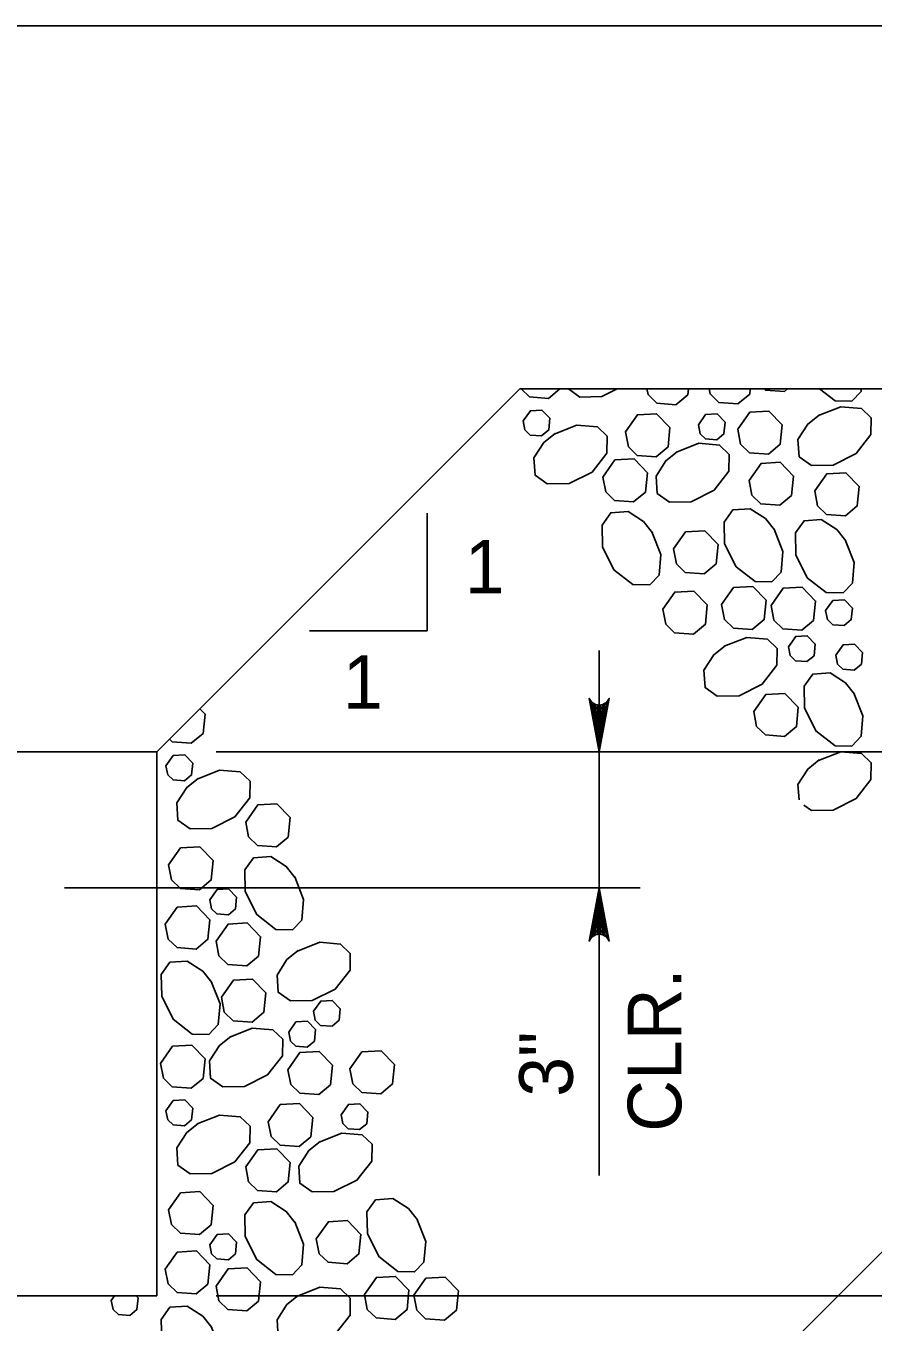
# Model space of a CAD drawing. Extents: x 638079 to 640019, y 297691 to 298879.
# Drawn here: x 639410.8 to 639458.2, y 298729 to 298801.6 of the extents above; entities that cross this region are included whole.
import ezdxf

# ---------------------------------------------------------------- set-up
doc = ezdxf.new("R2010")
doc.units = 0
doc.layers.add('1', color=7, linetype='Continuous')

msp = doc.modelspace()

# ---------------------------------------------------------------- linework, layer by layer
at = {"layer": '1'}
for p, q in [((639342.891, 298801.575), (639493.433, 298801.575)), ((639418.14, 298760.936), (639438.458, 298781.254)), ((639438.458, 298781.254), (639493.433, 298781.254)), ((639433.273, 298774.284), (639433.273, 298767.699)), ((639433.273, 298767.699), (639426.688, 298767.699)), ((639442.891, 298737.206), (639442.891, 298766.595)), ((639265.74, 298760.936), (639418.14, 298760.936)), ((639418.14, 298760.936), (639418.14, 298730.456)), ((639421.456, 298760.936), (639505.834, 298760.936)), ((639433.38, 298707.596), (639484.178, 298758.394)), ((639412.971, 298753.316), (639445.183, 298753.316)), ((639265.74, 298730.456), (639418.14, 298730.456)), ((639421.456, 298730.456), (639506.188, 298730.456))]:
    msp.add_line(p, q, dxfattribs=at)
msp.add_lwpolyline([(639488.261, 298789.413), (639493.433, 298791.946), (639493.433, 298801.575), (639342.891, 298801.575), (639342.891, 298799.67), (639341.94, 298799.67), (639341.94, 298760.936), (639418.14, 298760.936), (639438.458, 298781.254), (639493.433, 298781.254), (639493.433, 298788.428), (639498.394, 298790.783)], close=True, dxfattribs=at)
for points in [[(639440.691, 298781.254), (639440.051, 298780.721), (639438.991, 298780.798), (639438.52, 298781.254)], [(639443.904, 298781.254), (639443.03, 298780.817), (639441.816, 298780.796), (639441.171, 298781.254)], [(639447.881, 298781.254), (639447.848, 298780.918), (639447.185, 298780.366), (639446.125, 298780.443), (639445.626, 298780.927), (639445.563, 298781.254)], [(639451.346, 298781.254), (639451.316, 298780.957), (639450.653, 298780.406), (639449.593, 298780.483), (639449.095, 298780.966), (639449.039, 298781.254)], [(639453.437, 298781.254), (639453.26, 298781.107), (639452.201, 298781.184), (639452.129, 298781.254)], [(639457.56, 298781.254), (639457.547, 298781.11), (639457.025, 298780.561), (639456.088, 298780.579), (639455.224, 298781.254)], [(639438.636, 298779.456), (639439.04, 298780.03), (639439.684, 298780.067), (639440.131, 298779.603), (639440.067, 298778.952), (639439.669, 298778.621), (639439.033, 298778.667), (639438.734, 298778.958), (639438.637, 298779.456)], [(639444.361, 298778.842), (639445.034, 298779.799), (639446.107, 298779.86), (639446.853, 298779.086), (639446.745, 298778.002), (639446.082, 298777.451), (639445.022, 298777.528), (639444.524, 298778.011), (639444.362, 298778.842)], [(639448.44, 298779.236), (639448.844, 298779.809), (639449.488, 298779.846), (639449.936, 298779.382), (639449.871, 298778.732), (639449.473, 298778.401), (639448.837, 298778.447), (639448.538, 298778.737), (639448.441, 298779.235)], [(639450.644, 298778.988), (639451.316, 298779.944), (639452.389, 298780.005), (639453.135, 298779.232), (639453.027, 298778.148), (639452.364, 298777.596), (639451.305, 298777.673), (639450.806, 298778.156), (639450.644, 298778.988)], [(639455.155, 298779.752), (639456.413, 298780.251), (639457.568, 298780.151), (639458.117, 298779.629), (639458.1, 298778.692), (639457.266, 298777.626), (639455.978, 298776.982), (639454.764, 298776.961), (639454.081, 298777.447), (639454.016, 298778.413), (639454.571, 298779.278), (639455.206, 298779.785)], [(639440.378, 298778.72), (639441.636, 298779.218), (639442.791, 298779.119), (639443.34, 298778.597), (639443.323, 298777.659), (639442.489, 298776.594), (639441.202, 298775.95), (639439.988, 298775.929), (639439.305, 298776.414), (639439.24, 298777.381), (639439.794, 298778.246), (639440.429, 298778.752)], [(639447.211, 298777.703), (639448.468, 298778.202), (639449.624, 298778.102), (639450.173, 298777.58), (639450.155, 298776.642), (639449.322, 298775.577), (639448.034, 298774.933), (639446.82, 298774.912), (639446.137, 298775.397), (639446.072, 298776.364), (639446.627, 298777.229), (639447.262, 298777.735)], [(639443.096, 298776.312), (639443.769, 298777.269), (639444.842, 298777.33), (639445.588, 298776.556), (639445.48, 298775.472), (639444.817, 298774.921), (639443.757, 298774.998), (639443.259, 298775.481), (639443.097, 298776.312)], [(639451.276, 298776.125), (639451.948, 298777.081), (639453.022, 298777.142), (639453.768, 298776.369), (639453.66, 298775.285), (639452.997, 298774.733), (639451.937, 298774.81), (639451.439, 298775.293), (639451.277, 298776.125)], [(639454.952, 298775.539), (639455.624, 298776.495), (639456.697, 298776.557), (639457.443, 298775.783), (639457.335, 298774.699), (639456.672, 298774.147), (639455.613, 298774.224), (639455.114, 298774.708), (639454.952, 298775.539)], [(639445.842, 298773.238), (639446.341, 298771.98), (639446.241, 298770.825), (639445.719, 298770.275), (639444.782, 298770.293), (639443.717, 298771.126), (639443.073, 298772.414), (639443.051, 298773.628), (639443.537, 298774.311), (639444.504, 298774.376), (639445.368, 298773.822), (639445.875, 298773.187)], [(639452.675, 298773.4), (639453.174, 298772.143), (639453.074, 298770.987), (639452.552, 298770.438), (639451.614, 298770.456), (639450.549, 298771.289), (639449.905, 298772.577), (639449.884, 298773.791), (639450.369, 298774.474), (639451.336, 298774.539), (639452.201, 298773.985), (639452.707, 298773.35)], [(639456.661, 298772.79), (639457.159, 298771.533), (639457.06, 298770.377), (639456.538, 298769.828), (639455.6, 298769.846), (639454.535, 298770.679), (639453.891, 298771.967), (639453.87, 298773.181), (639454.355, 298773.864), (639455.322, 298773.929), (639456.187, 298773.375), (639456.693, 298772.74)], [(639447.05, 298772.286), (639447.722, 298773.243), (639448.796, 298773.304), (639449.542, 298772.53), (639449.434, 298771.446), (639448.771, 298770.895), (639447.711, 298770.971), (639447.213, 298771.455), (639447.051, 298772.286)], [(639446.449, 298768.912), (639447.122, 298769.869), (639448.195, 298769.93), (639448.941, 298769.156), (639448.833, 298768.072), (639448.17, 298767.521), (639447.11, 298767.598), (639446.612, 298768.081), (639446.45, 298768.912)], [(639449.741, 298769.169), (639450.413, 298770.125), (639451.486, 298770.186), (639452.232, 298769.413), (639452.124, 298768.329), (639451.461, 298767.777), (639450.402, 298767.854), (639449.903, 298768.337), (639449.741, 298769.168)], [(639452.506, 298769.128), (639453.178, 298770.084), (639454.252, 298770.146), (639454.998, 298769.372), (639454.89, 298768.288), (639454.227, 298767.736), (639453.167, 298767.813), (639452.669, 298768.297), (639452.507, 298769.128)], [(639455.565, 298768.833), (639455.968, 298769.406), (639456.613, 298769.443), (639457.06, 298768.979), (639456.995, 298768.329), (639456.598, 298767.998), (639455.962, 298768.044), (639455.662, 298768.334), (639455.565, 298768.832)], [(639453.484, 298766.815), (639453.888, 298767.389), (639454.532, 298767.426), (639454.979, 298766.961), (639454.915, 298766.311), (639454.517, 298765.98), (639453.881, 298766.026), (639453.582, 298766.316), (639453.485, 298766.815)], [(639449.892, 298766.835), (639451.15, 298767.333), (639452.305, 298767.233), (639452.855, 298766.711), (639452.837, 298765.774), (639452.004, 298764.708), (639450.716, 298764.065), (639449.502, 298764.043), (639448.819, 298764.529), (639448.754, 298765.496), (639449.308, 298766.36), (639449.943, 298766.867)], [(639456.132, 298766.342), (639456.536, 298766.916), (639457.18, 298766.953), (639457.628, 298766.488), (639457.563, 298765.838), (639457.165, 298765.507), (639456.529, 298765.553), (639456.23, 298765.843), (639456.133, 298766.342)], [(639457.148, 298764.209), (639457.647, 298762.951), (639457.547, 298761.796), (639457.025, 298761.247), (639456.088, 298761.264), (639455.022, 298762.098), (639454.379, 298763.386), (639454.357, 298764.599), (639454.843, 298765.283), (639455.81, 298765.347), (639456.674, 298764.793), (639457.181, 298764.158)], [(639442.891, 298760.936), (639442.332, 298763.919), (639442.411, 298763.804), (639442.491, 298763.689), (639442.591, 298763.63), (639442.691, 298763.57), (639442.791, 298763.553), (639442.891, 298763.536), (639442.991, 298763.553), (639443.091, 298763.57), (639443.191, 298763.63), (639443.291, 298763.689), (639443.371, 298763.804), (639443.45, 298763.919), (639442.891, 298760.936), (639443.371, 298763.804), (639443.291, 298763.689), (639442.891, 298760.936), (639443.191, 298763.63), (639443.091, 298763.57), (639442.891, 298760.936), (639442.991, 298763.553), (639442.891, 298763.536), (639442.891, 298760.936), (639442.791, 298763.553), (639442.691, 298763.57), (639442.891, 298760.936), (639442.591, 298763.63), (639442.491, 298763.689), (639442.891, 298760.936), (639442.411, 298763.804)], [(639451.54, 298763.184), (639452.212, 298764.141), (639453.285, 298764.202), (639454.032, 298763.428), (639453.924, 298762.344), (639453.26, 298761.793), (639452.201, 298761.87), (639451.702, 298762.353), (639451.54, 298763.184)], [(639420.545, 298763.341), (639420.833, 298763.042), (639420.725, 298761.958), (639420.062, 298761.407), (639419.002, 298761.483), (639418.842, 298761.638)], [(639455.155, 298760.438), (639456.413, 298760.936), (639457.568, 298760.837), (639458.117, 298760.315), (639458.1, 298759.377), (639457.266, 298758.312), (639455.978, 298757.668), (639454.764, 298757.647), (639454.339, 298757.949)], [(639418.648, 298760.142), (639419.051, 298760.716), (639419.695, 298760.752), (639420.143, 298760.288), (639420.078, 298759.638), (639419.68, 298759.307), (639419.044, 298759.353), (639418.745, 298759.643), (639418.648, 298760.142)], [(639454.074, 298758.243), (639454.016, 298759.099), (639454.571, 298759.964), (639455.206, 298760.47)], [(639420.39, 298759.405), (639421.647, 298759.904), (639422.803, 298759.804), (639423.352, 298759.282), (639423.334, 298758.345), (639422.501, 298757.279), (639421.213, 298756.635), (639419.999, 298756.614), (639419.316, 298757.1), (639419.251, 298758.066), (639419.806, 298758.931), (639420.441, 298759.438)], [(639423.108, 298756.998), (639423.78, 298757.954), (639424.853, 298758.016), (639425.6, 298757.242), (639425.492, 298756.158), (639424.829, 298755.606), (639423.769, 298755.683), (639423.27, 298756.167), (639423.108, 298756.998)], [(639418.797, 298754.598), (639419.469, 298755.555), (639420.542, 298755.616), (639421.289, 298754.842), (639421.181, 298753.758), (639420.518, 298753.207), (639419.458, 298753.283), (639418.959, 298753.767), (639418.797, 298754.598)], [(639425.854, 298753.923), (639426.353, 298752.666), (639426.253, 298751.51), (639425.731, 298750.961), (639424.793, 298750.979), (639423.728, 298751.812), (639423.084, 298753.1), (639423.063, 298754.314), (639423.548, 298754.997), (639424.515, 298755.061), (639425.38, 298754.507), (639425.886, 298753.872)], [(639421.107, 298752.639), (639421.51, 298753.213), (639422.154, 298753.25), (639422.602, 298752.785), (639422.537, 298752.135), (639422.139, 298751.804), (639421.503, 298751.85), (639421.204, 298752.14), (639421.107, 298752.639)], [(639442.891, 298753.316), (639443.45, 298750.333), (639443.371, 298750.448), (639443.291, 298750.563), (639443.191, 298750.622), (639443.091, 298750.682), (639442.991, 298750.699), (639442.891, 298750.716), (639442.791, 298750.699), (639442.691, 298750.682), (639442.591, 298750.622), (639442.491, 298750.563), (639442.411, 298750.448), (639442.332, 298750.333), (639442.891, 298753.316), (639442.411, 298750.448), (639442.491, 298750.563), (639442.891, 298753.316), (639442.591, 298750.622), (639442.691, 298750.682), (639442.891, 298753.316), (639442.791, 298750.699), (639442.891, 298750.716), (639442.891, 298753.316), (639442.991, 298750.699), (639443.091, 298750.682), (639442.891, 298753.316), (639443.191, 298750.622), (639443.291, 298750.563), (639442.891, 298753.316), (639443.371, 298750.448)], [(639418.609, 298751.278), (639419.281, 298752.234), (639420.354, 298752.295), (639421.1, 298751.522), (639420.992, 298750.437), (639420.329, 298749.886), (639419.269, 298749.963), (639418.771, 298750.446), (639418.609, 298751.277)], [(639421.449, 298750.328), (639422.122, 298751.284), (639423.195, 298751.346), (639423.941, 298750.572), (639423.833, 298749.488), (639423.17, 298748.936), (639422.11, 298749.013), (639421.612, 298749.497), (639421.45, 298750.328)], [(639426.002, 298749.767), (639427.26, 298750.265), (639428.415, 298750.165), (639428.964, 298749.643), (639428.947, 298748.706), (639428.113, 298747.641), (639426.825, 298746.997), (639425.612, 298746.975), (639424.928, 298747.461), (639424.864, 298748.428), (639425.418, 298749.292), (639426.053, 298749.799)], [(639421.177, 298748.067), (639421.676, 298746.809), (639421.576, 298745.654), (639421.054, 298745.105), (639420.116, 298745.122), (639419.051, 298745.956), (639418.407, 298747.243), (639418.386, 298748.457), (639418.871, 298749.14), (639419.838, 298749.205), (639420.703, 298748.651), (639421.209, 298748.016)], [(639421.748, 298747.182), (639422.421, 298748.138), (639423.494, 298748.199), (639424.24, 298747.426), (639424.132, 298746.342), (639423.469, 298745.79), (639422.409, 298745.867), (639421.911, 298746.35), (639421.749, 298747.182)], [(639426.907, 298746.397), (639427.311, 298746.971), (639427.955, 298747.008), (639428.402, 298746.544), (639428.338, 298745.893), (639427.94, 298745.562), (639427.304, 298745.608), (639427.005, 298745.898), (639426.908, 298746.397)], [(639425.52, 298745.231), (639425.924, 298745.805), (639426.568, 298745.841), (639427.015, 298745.377), (639426.951, 298744.727), (639426.553, 298744.396), (639425.917, 298744.442), (639425.618, 298744.732), (639425.521, 298745.231)], [(639422.218, 298744.958), (639423.476, 298745.457), (639424.631, 298745.357), (639425.18, 298744.835), (639425.163, 298743.897), (639424.329, 298742.832), (639423.042, 298742.188), (639421.828, 298742.167), (639421.145, 298742.652), (639421.08, 298743.619), (639421.634, 298744.484), (639422.269, 298744.99)], [(639418.341, 298743.484), (639419.014, 298744.44), (639420.087, 298744.501), (639420.833, 298743.728), (639420.725, 298742.644), (639420.062, 298742.092), (639419.002, 298742.169), (639418.504, 298742.652), (639418.342, 298743.484)], [(639425.475, 298743.129), (639426.148, 298744.085), (639427.221, 298744.147), (639427.967, 298743.373), (639427.859, 298742.289), (639427.196, 298741.737), (639426.136, 298741.814), (639425.638, 298742.298), (639425.476, 298743.129)], [(639428.944, 298743.169), (639429.616, 298744.125), (639430.69, 298744.186), (639431.436, 298743.413), (639431.328, 298742.328), (639430.665, 298741.777), (639429.605, 298741.854), (639429.106, 298742.337), (639428.945, 298743.168)], [(639418.648, 298740.827), (639419.051, 298741.401), (639419.695, 298741.438), (639420.143, 298740.974), (639420.078, 298740.323), (639419.68, 298739.992), (639419.044, 298740.038), (639418.745, 298740.329), (639418.648, 298740.827)], [(639424.373, 298740.213), (639425.045, 298741.17), (639426.118, 298741.231), (639426.865, 298740.457), (639426.757, 298739.373), (639426.094, 298738.822), (639425.034, 298738.899), (639424.535, 298739.382), (639424.373, 298740.213)], [(639428.452, 298740.607), (639428.855, 298741.18), (639429.499, 298741.217), (639429.947, 298740.753), (639429.882, 298740.103), (639429.485, 298739.772), (639428.848, 298739.818), (639428.549, 298740.108), (639428.452, 298740.606)], [(639420.39, 298740.091), (639421.647, 298740.589), (639422.803, 298740.49), (639423.352, 298739.968), (639423.334, 298739.03), (639422.501, 298737.965), (639421.213, 298737.321), (639419.999, 298737.3), (639419.316, 298737.785), (639419.251, 298738.752), (639419.806, 298739.617), (639420.441, 298740.123)], [(639427.222, 298739.074), (639428.48, 298739.573), (639429.635, 298739.473), (639430.184, 298738.951), (639430.167, 298738.013), (639429.333, 298736.948), (639428.045, 298736.304), (639426.832, 298736.283), (639426.148, 298736.768), (639426.084, 298737.735), (639426.638, 298738.6), (639427.273, 298739.106)], [(639423.108, 298737.683), (639423.78, 298738.64), (639424.853, 298738.701), (639425.6, 298737.927), (639425.492, 298736.843), (639424.829, 298736.292), (639423.769, 298736.369), (639423.27, 298736.852), (639423.108, 298737.683)], [(639418.797, 298735.284), (639419.469, 298736.24), (639420.542, 298736.301), (639421.289, 298735.528), (639421.181, 298734.444), (639420.518, 298733.892), (639419.458, 298733.969), (639418.959, 298734.453), (639418.797, 298735.284)], [(639425.854, 298734.609), (639426.353, 298733.351), (639426.253, 298732.196), (639425.731, 298731.646), (639424.793, 298731.664), (639423.728, 298732.497), (639423.084, 298733.785), (639423.063, 298734.999), (639423.548, 298735.682), (639424.515, 298735.747), (639425.38, 298735.193), (639425.886, 298734.558)], [(639432.687, 298734.771), (639433.185, 298733.514), (639433.085, 298732.358), (639432.563, 298731.809), (639431.626, 298731.827), (639430.561, 298732.66), (639429.917, 298733.948), (639429.895, 298735.162), (639430.381, 298735.845), (639431.348, 298735.91), (639432.212, 298735.356), (639432.719, 298734.721)], [(639427.062, 298733.657), (639427.734, 298734.614), (639428.807, 298734.675), (639429.554, 298733.901), (639429.446, 298732.817), (639428.783, 298732.266), (639427.723, 298732.342), (639427.224, 298732.826), (639427.062, 298733.657)], [(639421.107, 298733.324), (639421.51, 298733.898), (639422.154, 298733.935), (639422.602, 298733.471), (639422.537, 298732.82), (639422.139, 298732.489), (639421.503, 298732.536), (639421.204, 298732.826), (639421.107, 298733.324)], [(639418.609, 298731.963), (639419.281, 298732.919), (639420.354, 298732.981), (639421.1, 298732.207), (639420.992, 298731.123), (639420.329, 298730.571), (639419.269, 298730.648), (639418.771, 298731.132), (639418.609, 298731.963)], [(639421.449, 298731.014), (639422.122, 298731.97), (639423.195, 298732.031), (639423.941, 298731.258), (639423.833, 298730.173), (639423.17, 298729.622), (639422.11, 298729.699), (639421.612, 298730.182), (639421.45, 298731.013)], [(639429.752, 298730.54), (639430.424, 298731.496), (639431.498, 298731.557), (639432.244, 298730.784), (639432.136, 298729.7), (639431.473, 298729.148), (639430.413, 298729.225), (639429.915, 298729.708), (639429.753, 298730.539)], [(639432.518, 298730.499), (639433.19, 298731.455), (639434.263, 298731.517), (639435.01, 298730.743), (639434.902, 298729.659), (639434.238, 298729.107), (639433.179, 298729.184), (639432.68, 298729.668), (639432.518, 298730.499)], [(639415.588, 298730.204), (639415.766, 298730.456)], [(639416.981, 298730.456), (639417.083, 298730.35), (639417.018, 298729.7), (639416.621, 298729.369), (639415.985, 298729.415), (639415.685, 298729.705), (639415.588, 298730.203)], [(639426.002, 298730.452), (639427.26, 298730.951), (639428.415, 298730.851), (639428.964, 298730.329), (639428.947, 298729.391), (639428.113, 298728.326), (639426.825, 298727.682), (639425.612, 298727.661), (639424.928, 298728.146), (639424.864, 298729.113), (639425.418, 298729.978), (639426.053, 298730.484)], [(639421.177, 298728.752), (639421.676, 298727.495), (639421.576, 298726.339), (639421.054, 298725.79), (639420.116, 298725.808), (639419.051, 298726.641), (639418.407, 298727.929), (639418.386, 298729.143), (639418.871, 298729.826), (639419.838, 298729.891), (639420.703, 298729.336), (639421.209, 298728.701)]]:
    msp.add_lwpolyline(points, dxfattribs=at)

# ---------------------------------------------------------------- texts
for p in [(639435.366, 298769.798), (639428.548, 298763.339)]:
    msp.add_text('1', height=3, dxfattribs=at).set_placement(p)
for s, p in [('CLR.', (639447.486, 298739.653)), ('3"', (639441.414, 298741.613))]:
    msp.add_text(s, height=3, rotation=90, dxfattribs=at).set_placement(p)

doc.saveas('drawing.dxf')
